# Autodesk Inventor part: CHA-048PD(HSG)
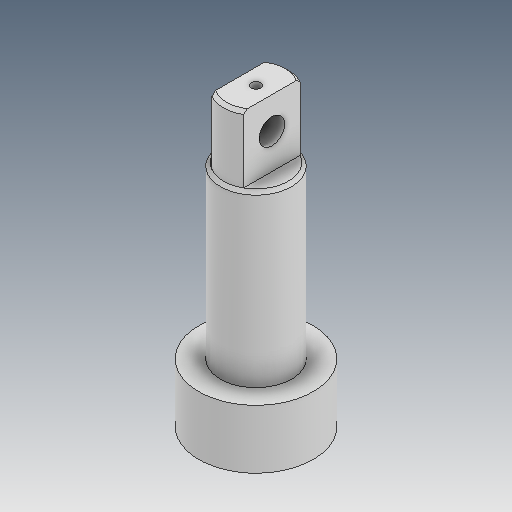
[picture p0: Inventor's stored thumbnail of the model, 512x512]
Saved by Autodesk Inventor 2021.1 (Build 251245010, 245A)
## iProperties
Created: 2021-05
Part Number: CHA-048PD(HSG)
Material: Ogólny
Document SubType Name: Modeling
Designer: user
Density: 1 g/cm^3
Appearance: Domyślna
Author: user
Revision Number: ÈÎºÎ
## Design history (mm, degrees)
feature "M4 ÂÝÎÆ¿×1"
node "Bryła1"
